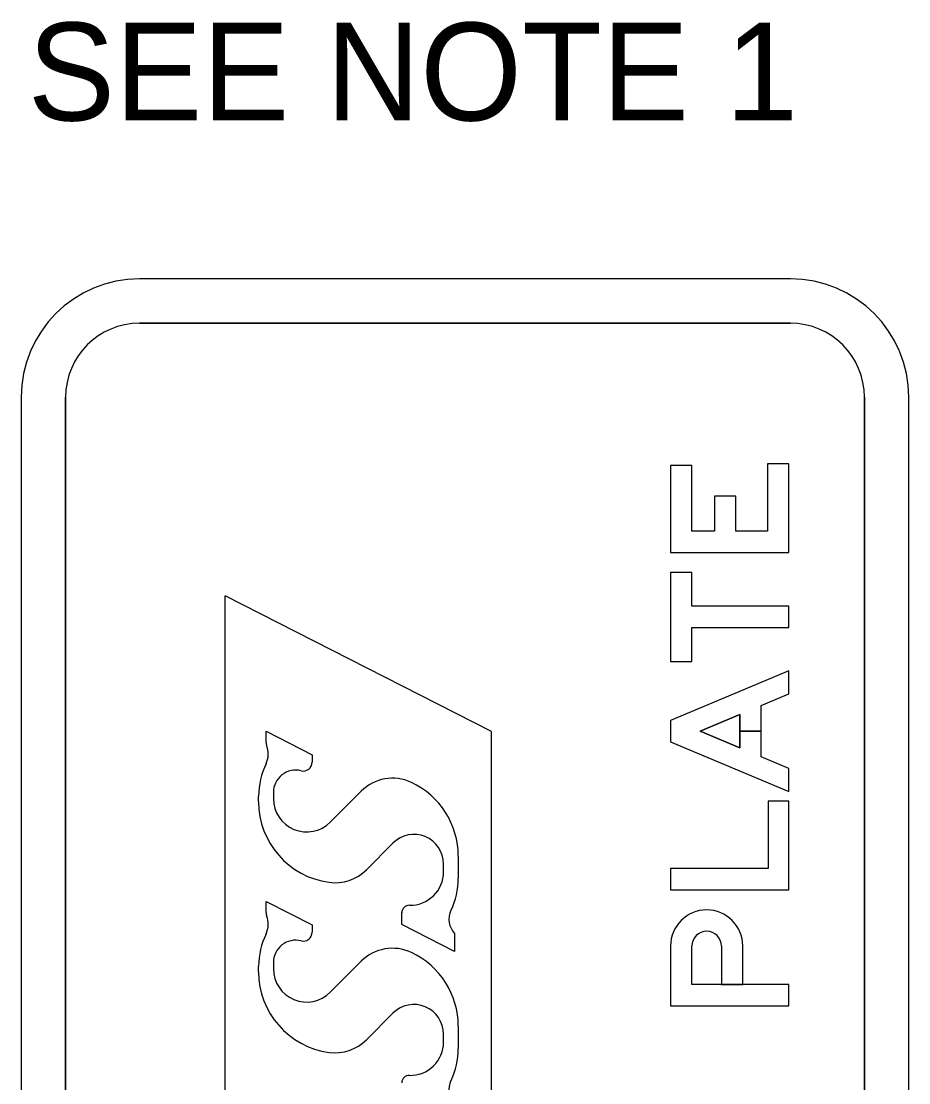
# Model space of a CAD drawing. Extents: x 46672 to 47298, y 5424 to 5829.
# Drawn here: x 47074.71 to 47100.12, y 5720.48 to 5750.87 of the extents above; entities that cross this region are included whole.
import ezdxf

# ---------------------------------------------------------------- set-up
doc = ezdxf.new("R2010")
doc.units = 0
doc.layers.add('SignPanel', color=7, linetype='Continuous')
doc.layers.add('TextLabel', color=7, linetype='Continuous')

msp = doc.modelspace()

# ---------------------------------------------------------------- linework, layer by layer
at = {"layer": 'SignPanel'}
for p, q in [((47096.729, 5743.492), (47078.095, 5743.492)), ((47096.729, 5743.492), (47078.095, 5743.492)), ((47096.729, 5743.492), (47078.095, 5743.492)), ((47096.729, 5743.492), (47078.095, 5743.492)), ((47096.729, 5742.221), (47078.095, 5742.221)), ((47078.095, 5742.221), (47096.729, 5742.221)), ((47078.095, 5742.221), (47096.729, 5742.221)), ((47074.707, 5740.104), (47074.707, 5685.894)), ((47074.707, 5740.104), (47074.707, 5685.894)), ((47074.707, 5740.104), (47074.707, 5685.894)), ((47074.707, 5740.104), (47074.707, 5685.894)), ((47075.977, 5740.104), (47075.977, 5685.894)), ((47075.977, 5685.894), (47075.977, 5740.104)), ((47075.977, 5685.894), (47075.977, 5740.104)), ((47098.847, 5685.894), (47098.847, 5740.104)), ((47098.847, 5740.104), (47098.847, 5685.907)), ((47098.847, 5740.104), (47098.847, 5685.907)), ((47100.118, 5685.894), (47100.118, 5740.104)), ((47100.118, 5685.894), (47100.118, 5740.104)), ((47100.118, 5685.907), (47100.118, 5740.104)), ((47100.118, 5685.907), (47100.118, 5740.104)), ((47088.172, 5730.532), (47080.55, 5734.416)), ((47080.55, 5710.261), (47080.55, 5734.416)), ((47081.715, 5730.225), (47081.715, 5730.543)), ((47081.715, 5730.543), (47083.036, 5729.87)), ((47088.172, 5709.7), (47088.172, 5730.532)), ((47083.036, 5729.87), (47083.036, 5729.658)), ((47083.553, 5727.942), (47084.44, 5728.829)), ((47081.503, 5728.529), (47081.503, 5728.689)), ((47081.927, 5728.796), (47081.927, 5728.615)), ((47085.35, 5727.343), (47084.588, 5726.581)), ((47086.796, 5726.516), (47086.796, 5726.744)), ((47087.22, 5726.972), (47087.22, 5726.334)), ((47081.715, 5725.356), (47081.715, 5725.674)), ((47081.715, 5725.674), (47083.036, 5725.001)), ((47085.604, 5725.011), (47085.604, 5725.352)), ((47083.036, 5725.001), (47083.036, 5724.789)), ((47087.113, 5724.243), (47085.604, 5725.011)), ((47087.113, 5724.758), (47087.113, 5724.243)), ((47093.907, 5723.295), (47093.907, 5724.397)), ((47093.907, 5723.295), (47093.907, 5724.397)), ((47093.907, 5723.295), (47093.907, 5724.397)), ((47095.364, 5723.295), (47095.364, 5724.397)), ((47083.553, 5723.072), (47084.44, 5723.959)), ((47081.503, 5723.659), (47081.503, 5723.819)), ((47081.927, 5723.927), (47081.927, 5723.746)), ((47085.35, 5722.474), (47084.588, 5721.712)), ((47086.796, 5721.646), (47086.796, 5721.875)), ((47087.22, 5722.103), (47087.22, 5721.466))]:
    msp.add_line(p, q, dxfattribs=at)
for points in [[(47096.076, 5738.203), (47096.076, 5736.272), (47095.165, 5736.272), (47095.165, 5737.271), (47094.555, 5737.271), (47094.555, 5736.272), (47093.907, 5736.272), (47093.907, 5738.152), (47093.298, 5738.152), (47093.298, 5735.662), (47096.686, 5735.662), (47096.686, 5738.203)], [(47096.076, 5738.203), (47096.076, 5736.272), (47095.165, 5736.272), (47095.165, 5737.271), (47094.555, 5737.271), (47094.555, 5736.272), (47093.907, 5736.272), (47093.907, 5738.152), (47093.298, 5738.152), (47093.298, 5735.662), (47096.686, 5735.662), (47096.686, 5738.203)], [(47096.076, 5738.203), (47096.076, 5736.272), (47095.165, 5736.272), (47095.165, 5737.271), (47094.555, 5737.271), (47094.555, 5736.272), (47093.907, 5736.272), (47093.907, 5738.152), (47093.298, 5738.152), (47093.298, 5735.662), (47096.686, 5735.662), (47096.686, 5738.203)], [(47093.907, 5732.545), (47093.907, 5733.511), (47096.686, 5733.511), (47096.686, 5734.12), (47093.907, 5734.12), (47093.907, 5735.086), (47093.298, 5735.086), (47093.298, 5732.545)], [(47093.907, 5732.545), (47093.907, 5733.511), (47096.686, 5733.511), (47096.686, 5734.12), (47093.907, 5734.12), (47093.907, 5735.086), (47093.298, 5735.086), (47093.298, 5732.545)], [(47093.907, 5732.545), (47093.907, 5733.511), (47096.686, 5733.511), (47096.686, 5734.12), (47093.907, 5734.12), (47093.907, 5735.086), (47093.298, 5735.086), (47093.298, 5732.545)], [(47095.89, 5729.814), (47095.89, 5731.278), (47096.686, 5731.612), (47096.686, 5732.274), (47093.298, 5730.851), (47093.298, 5730.241), (47096.686, 5728.818), (47096.686, 5729.479)], [(47095.28, 5731.022), (47095.28, 5730.546), (47095.89, 5730.546), (47095.89, 5731.278), (47096.686, 5731.612), (47096.686, 5732.274), (47093.298, 5730.851), (47093.298, 5730.241), (47096.686, 5728.818), (47096.686, 5729.479), (47095.89, 5729.814), (47095.89, 5730.546), (47095.28, 5730.546), (47095.28, 5730.07), (47094.146, 5730.546)], [(47095.28, 5731.022), (47095.28, 5730.546), (47095.89, 5730.546), (47095.89, 5731.278), (47096.686, 5731.612), (47096.686, 5732.274), (47093.298, 5730.851), (47093.298, 5730.241), (47096.686, 5728.818), (47096.686, 5729.479), (47095.89, 5729.814), (47095.89, 5730.546), (47095.28, 5730.546), (47095.28, 5730.07), (47094.146, 5730.546)], [(47095.28, 5731.022), (47094.146, 5730.546), (47095.28, 5730.07)], [(47096.686, 5728.547), (47096.093, 5728.547), (47096.093, 5726.616), (47093.298, 5726.616), (47093.298, 5726.006), (47096.686, 5726.006)], [(47096.686, 5728.547), (47096.093, 5728.547), (47096.093, 5726.616), (47093.298, 5726.616), (47093.298, 5726.006), (47096.686, 5726.006)], [(47096.686, 5728.547), (47096.093, 5728.547), (47096.093, 5726.616), (47093.298, 5726.616), (47093.298, 5726.006), (47096.686, 5726.006)]]:
    msp.add_lwpolyline(points, close=True, dxfattribs=at)
for points in [[(47093.298, 5724.397), (47093.298, 5722.686), (47096.686, 5722.686), (47096.686, 5723.295), (47095.364, 5723.295)], [(47093.298, 5724.397), (47093.298, 5722.686), (47096.686, 5722.686), (47096.686, 5723.295), (47093.907, 5723.295)], [(47093.298, 5724.397), (47093.298, 5722.686), (47096.686, 5722.686), (47096.686, 5723.295), (47093.907, 5723.295)], [(47094.754, 5724.397), (47094.754, 5723.295), (47093.907, 5723.295)], [(47094.754, 5724.397), (47094.754, 5723.296), (47095.364, 5723.296), (47095.364, 5724.397)], [(47094.754, 5724.397), (47094.754, 5723.296), (47095.364, 5723.296), (47095.364, 5724.397)]]:
    msp.add_lwpolyline(points, dxfattribs=at)
for centre, radius, start, end in [((47078.095, 5740.104), 3.388, 90, 180), ((47078.095, 5740.104), 3.388, 90, 180), ((47078.095, 5740.104), 3.388, 90, 180), ((47078.095, 5740.104), 3.388, 90, 180), ((47096.729, 5740.104), 3.388, 360, 90), ((47096.729, 5740.104), 3.388, 360, 90), ((47096.729, 5740.104), 3.388, 360, 90), ((47096.729, 5740.104), 3.388, 360, 90), ((47078.095, 5740.104), 2.118, 90, 180), ((47078.095, 5740.104), 2.118, 90, 180), ((47078.095, 5740.104), 2.118, 90, 180), ((47096.729, 5740.104), 2.118, 360, 90), ((47096.729, 5740.104), 2.118, 360, 90), ((47096.729, 5740.104), 2.118, 360, 90), ((47081.969, 5730.225), 0.254, 180, 202.0347), ((47081.145, 5729.891), 0.635, 334.0896, 22.0347), ((47083.621, 5728.689), 2.117, 154.0896, 180), ((47082.562, 5728.796), 0.635, 75.6915, 180), ((47082.782, 5729.658), 0.254, 255.6915, 360), ((47085.339, 5727.93), 1.27, 64.95, 135), ((47084.891, 5726.971), 2.329, 360, 64.95), ((47083.832, 5728.528), 2.329, 180, 262.3089), ((47082.88, 5728.615), 0.953, 180, 315), ((47085.949, 5726.744), 0.847, 360, 135), ((47083.691, 5727.479), 1.27, 262.3089, 315), ((47085.844, 5726.516), 0.953, 268.6664, 360), ((47085.103, 5726.334), 2.117, 334.3795, 0), ((47085.816, 5725.351), 0.212, 88.6664, 180), ((47081.969, 5725.356), 0.254, 180, 202.0347), ((47081.145, 5725.022), 0.635, 334.0896, 22.0347), ((47087.546, 5725.163), 0.593, 154.3795, 223.1892), ((47083.621, 5723.819), 2.117, 154.0896, 180), ((47082.782, 5724.789), 0.254, 255.6915, 360), ((47082.562, 5723.927), 0.635, 75.6915, 180), ((47085.339, 5723.061), 1.27, 64.95, 135), ((47084.891, 5722.102), 2.329, 360, 64.95), ((47083.832, 5723.659), 2.329, 180, 262.3089), ((47082.88, 5723.745), 0.953, 180, 315), ((47085.949, 5721.875), 0.847, 360, 135), ((47083.691, 5722.61), 1.27, 262.3089, 315), ((47085.844, 5721.646), 0.953, 268.6664, 360), ((47085.103, 5721.465), 2.117, 334.3795, 0), ((47085.816, 5720.482), 0.212, 88.6664, 180), ((47087.546, 5720.293), 0.593, 154.3795, 223.1892)]:
    msp.add_arc(centre, radius, start, end, dxfattribs=at)
for major_axis in [(-1.033, 0), (-1.033, 0), (-1.033, 0), (-0.424, 0), (-0.424, 0), (-0.424, 0)]:
    msp.add_ellipse((47094.331, 5724.397), major_axis=major_axis, ratio=0.999994, start_param=3.141593, end_param=6.283185, dxfattribs=at)

# ---------------------------------------------------------------- texts
at = {"layer": 'TextLabel'}
msp.add_text('SEE NOTE 1', height=2.8, dxfattribs=at).set_placement((47074.894, 5748.026))

doc.saveas('drawing.dxf')
